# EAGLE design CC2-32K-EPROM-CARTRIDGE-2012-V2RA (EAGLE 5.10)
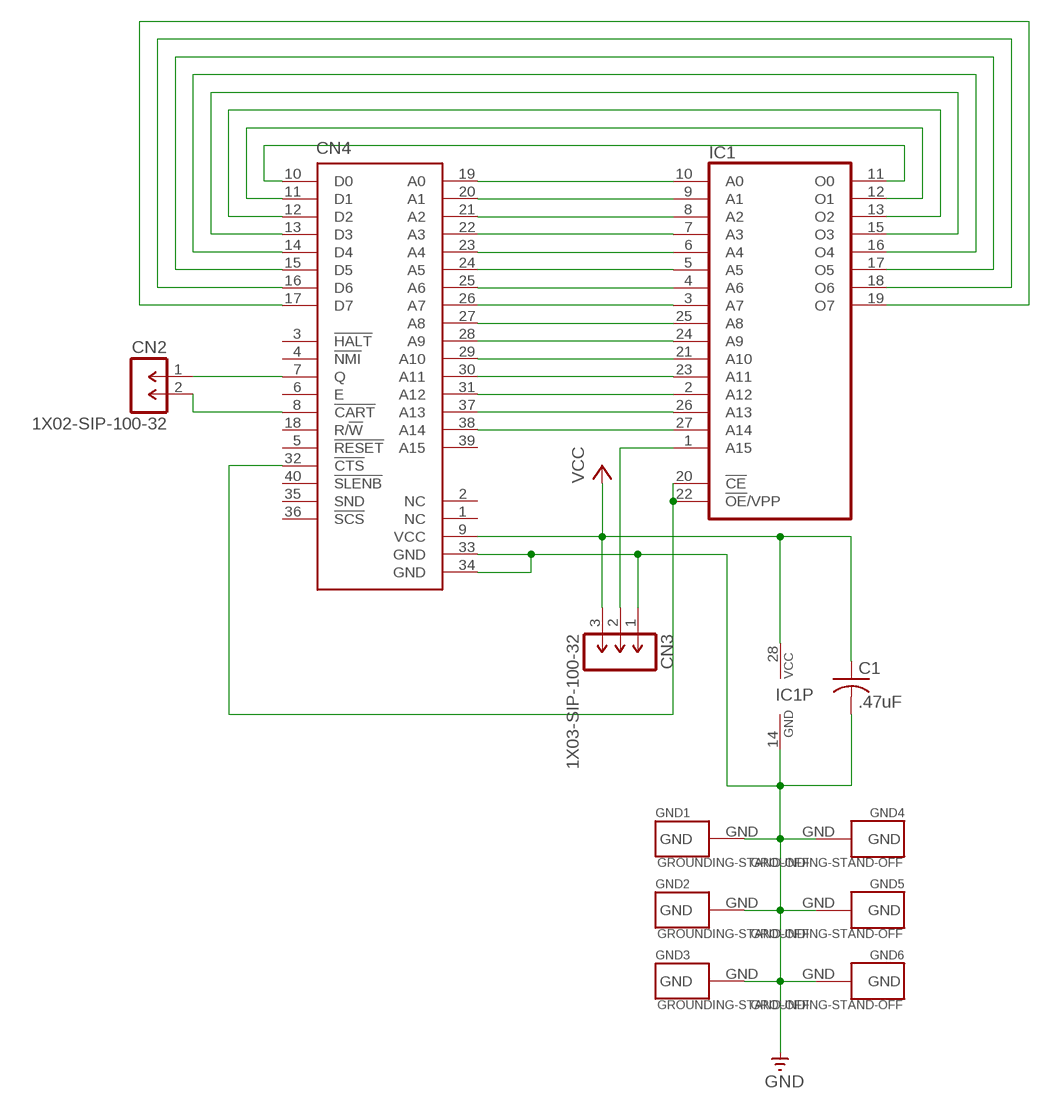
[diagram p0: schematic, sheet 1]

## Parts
C1  .47uF  NP-CAPACITOR-C050-025X075  [C050-025X075]
CN2  1X02-SIP-100-32  [SIL1X02-100]
CN3  1X03-SIP-100-32  [SIL1X03-100]
CN4  COCO3-CARTRIDGE-PLUG-SHORT  [EDGE-CARD-PLUG-2X20-100-SHORT]
GND1  GROUNDING-STAND-OFF  [STAND-OFF]
GND2  GROUNDING-STAND-OFF  [STAND-OFF]
GND3  GROUNDING-STAND-OFF  [STAND-OFF]
GND4  GROUNDING-STAND-OFF  [STAND-OFF]
GND5  GROUNDING-STAND-OFF  [STAND-OFF]
GND6  GROUNDING-STAND-OFF  [STAND-OFF]
IC1  27C512D-MINIMAL-OUTLINE  [DIL28-6-MINIMAL-OUTLINE]

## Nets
GND [power]: C1.2(-) CN3.1 CN4.33(GND) CN4.34(GND) GND1.GND GND2.GND GND3.GND GND4.GND GND5.GND GND6.GND IC1.14(GND)
N$2: CN2.1 CN4.7(Q)
N$3: CN2.2 CN4.8(!CART)
N$4: CN4.19(A0) IC1.10(A0)
N$5: CN4.20(A1) IC1.9(A1)
N$6: CN4.21(A2) IC1.8(A2)
N$7: CN4.22(A3) IC1.7(A3)
N$8: CN4.23(A4) IC1.6(A4)
N$9: CN4.24(A5) IC1.5(A5)
N$10: CN4.25(A6) IC1.4(A6)
N$11: CN4.26(A7) IC1.3(A7)
N$12: CN4.27(A8) IC1.25(A8)
N$13: CN4.28(A9) IC1.24(A9)
N$14: CN4.29(A10) IC1.21(A10)
N$15: CN4.30(A11) IC1.23(A11)
N$16: CN4.31(A12) IC1.2(A12)
N$17: CN4.37(A13) IC1.26(A13)
N$18: CN4.38(A14) IC1.27(A14)
N$19: CN3.2 IC1.1(A15)
N$21: CN4.10(D0) IC1.11(O0)
N$22: CN4.11(D1) IC1.12(O1)
N$23: CN4.12(D2) IC1.13(O2)
N$24: CN4.13(D3) IC1.15(O3)
N$25: CN4.14(D4) IC1.16(O4)
N$26: CN4.15(D5) IC1.17(O5)
N$27: CN4.16(D6) IC1.18(O6)
N$28: CN4.17(D7) IC1.19(O7)
N$29: CN4.32(!CTS) IC1.20(!CE) IC1.22(!OE!/VPP)
VCC [power]: C1.1(+) CN3.3 CN4.9(VCC) IC1.28(VCC)
Unconnected: CN4.1(NC) CN4.2(NC) CN4.3(!HALT) CN4.4(!NMI) CN4.5(!RESET) CN4.6(E) CN4.18(R/!W) CN4.35(SND) CN4.36(!SCS) CN4.39(A15) CN4.40(!SLENB)

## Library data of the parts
C1 = GIMEchip-Capacitor:NP-CAPACITOR: NON-POLARIZED CAPACITOR
CN2 = GIMEchip-Header-Generic:1X02: MALE HEADER
CN3 = GIMEchip-Header-Generic:1X03: MALE HEADER
CN4 = GIMEchip-TRS-80-CoCo-3-Program-Pak-Cartridge:COCO3-CARTRIDGE-PLUG: CoCo 3 Program Pak Cartridge Plug - http://www.GIMEchip.com/ Tandy Radio Shack TRS-80 Color Computer 3 Program Pak Cartridge Plug (Edge-Card) E.A.G.L.E. Library Part created by John Eric Turner & His Father - sales@gimechip.com 40-Pin Edge-Card sharing the same pinout as the Program Pak Cartridge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
GND1-GND6 = GIMEchip-Grounding:GROUNDING
IC1 = GIMEchip-EPROM:27C512D: MEMORY

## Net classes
0 default: width 0.203 mm, clearance 0.203 mm
1 power: width 0.762 mm, clearance 0.203 mm

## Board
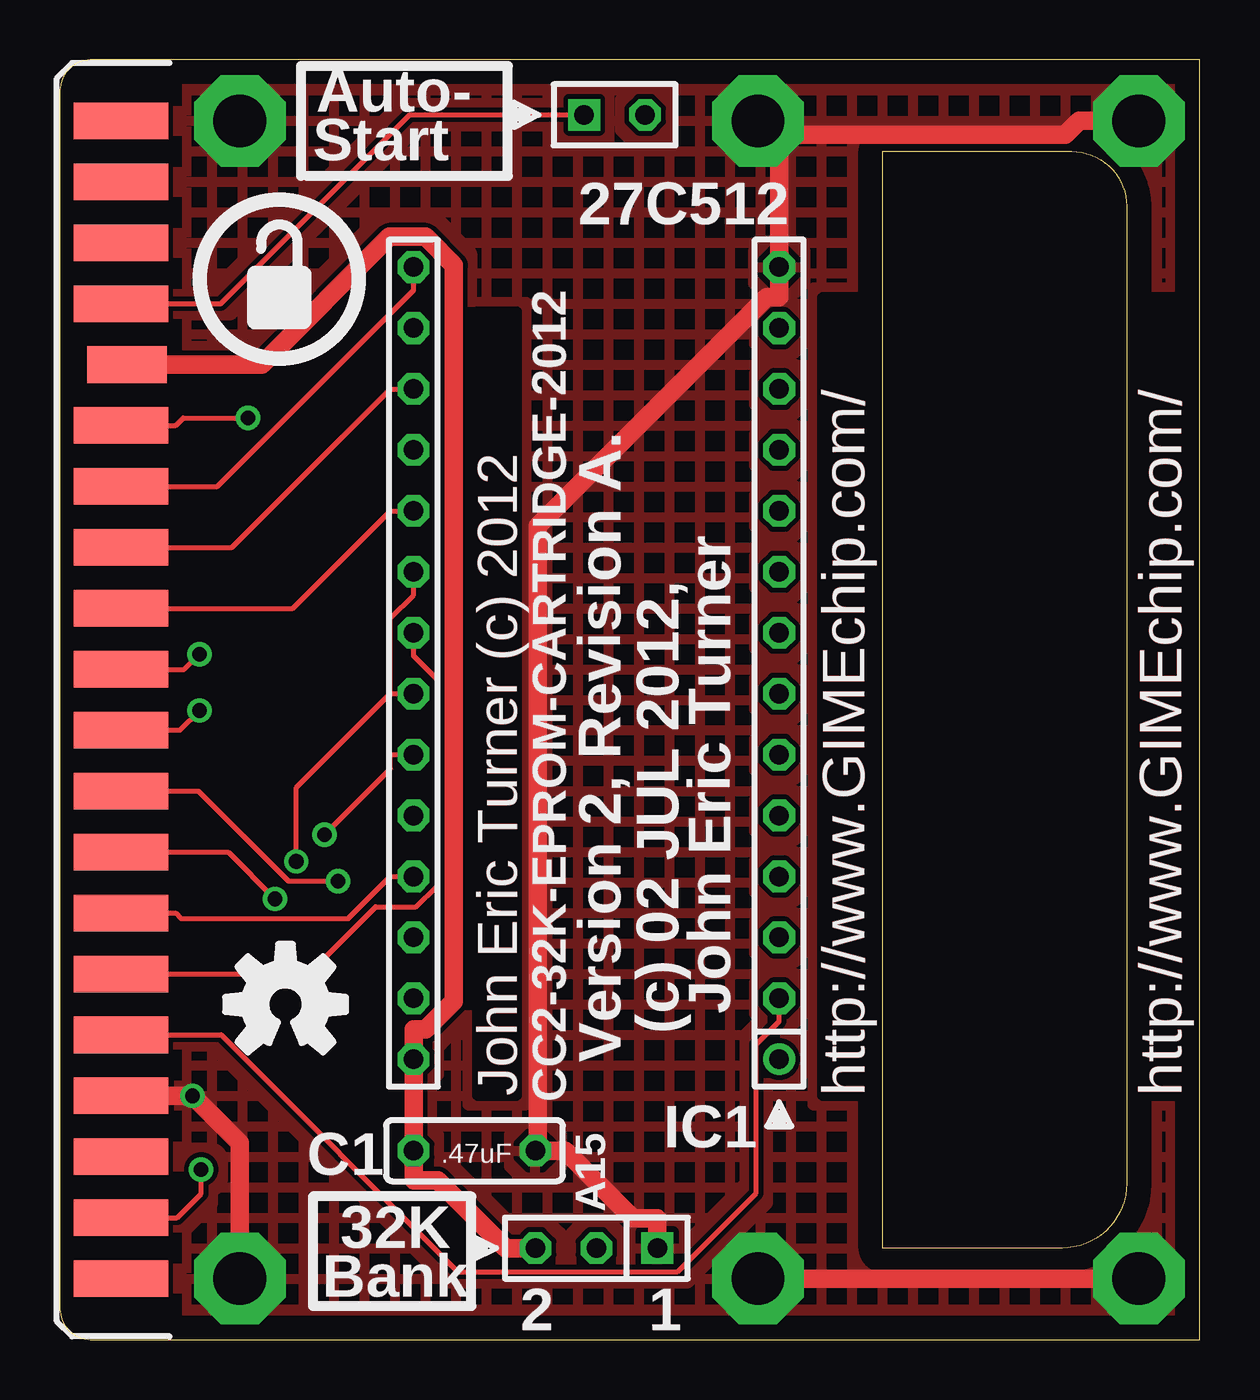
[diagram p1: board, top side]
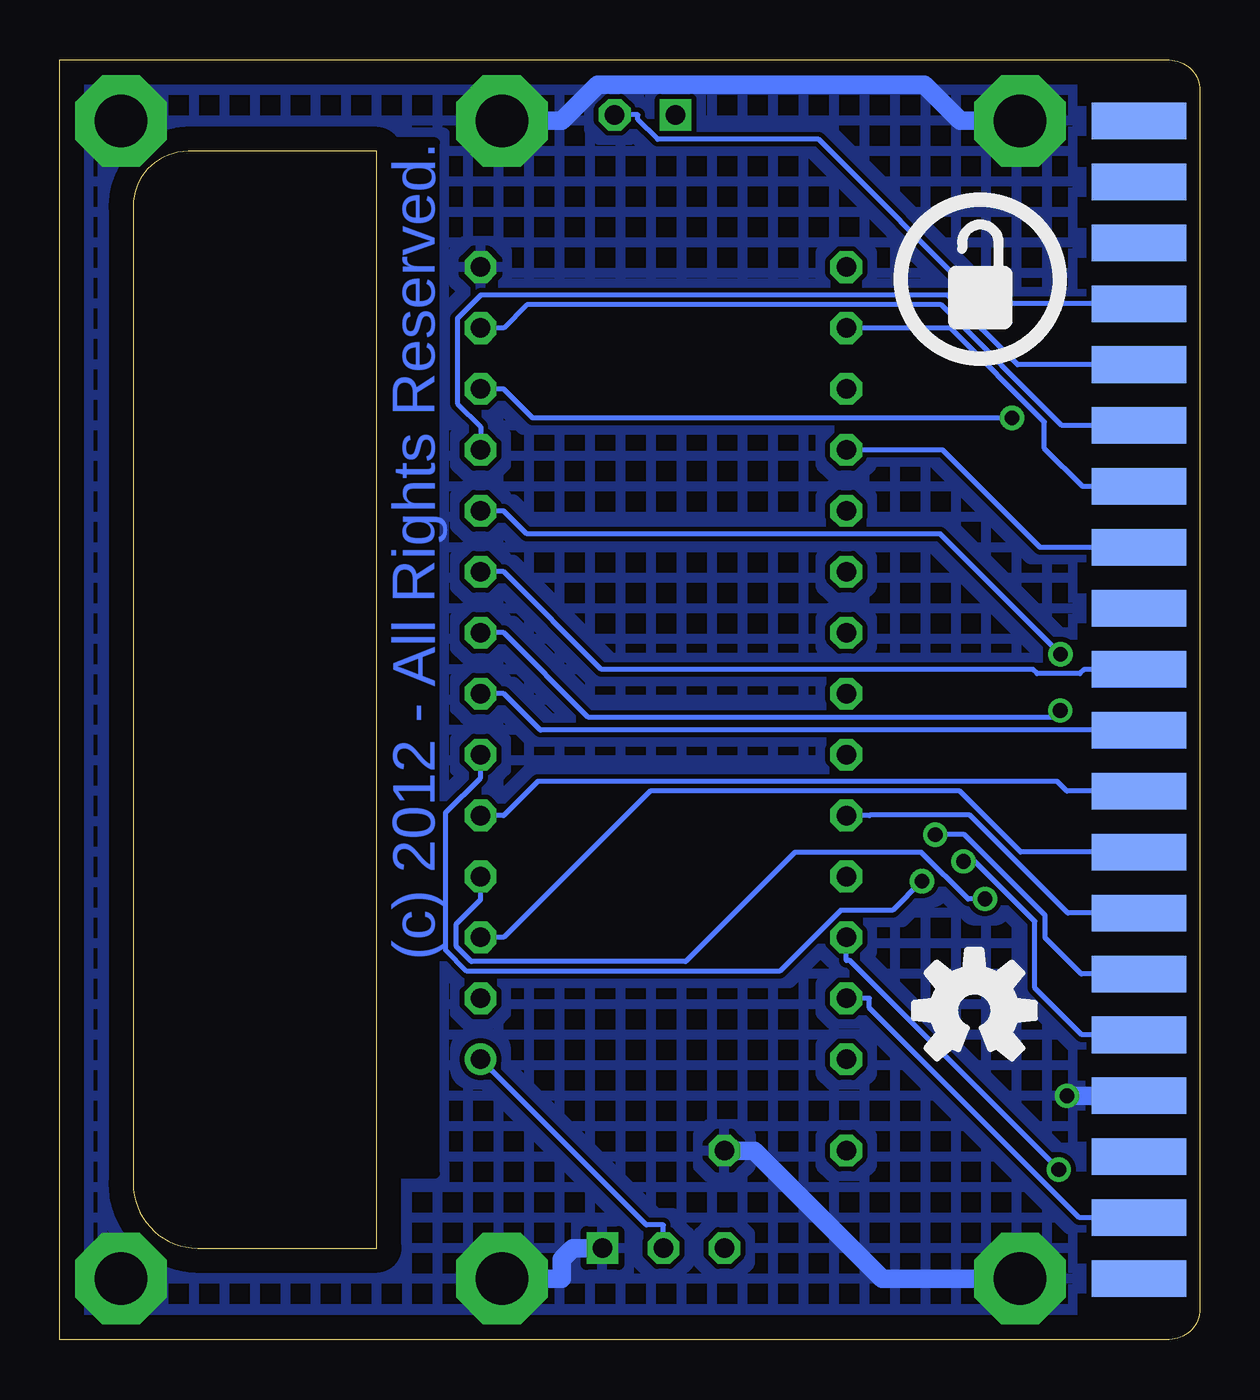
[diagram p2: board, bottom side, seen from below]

Size 47.5 x 53.34 mm. Coordinates in mm from the lower left corner, seen from the top.
Outline: 47.5,0 47.5,53.34 1.27,53.34 arc90 0,52.07 0,1.27 arc90 1.27,0 47.5,0
Outline: 34.29,49.53 42.16,49.53 arc-90 44.45,47.24 44.45,6.5 arc-90 41.76,3.81 34.29,3.81 34.29,49.53
Copper layers (1*16): Top 0.035mm / dielectric 1.5mm / Bottom 0.035mm
Design rules "default": minimum track width 10mil, minimum drill 24mil, track to track 8mil, track to pad 8mil, pad to pad 8mil, via to via 8mil, smd to smd 8mil, copper to edge 40mil, drill to drill 8mil, minimum pad ring 10mil, minimum via ring 8mil, stop-mask expansion 4mil, vias tented up to drill 0mil, thermal gap 10mil
vRestrict: area 15.2,8.9 to 29.2,49.5

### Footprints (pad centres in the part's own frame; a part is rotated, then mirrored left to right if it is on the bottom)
C050-025X075 = drill 0.813 octagon: 1 -2.54,0; 2 2.54,0
SIL1X02-100 = drill 0.813 square: 1 -1.27,0 | drill 0.813 octagon: 2 1.27,0
SIL1X03-100 = drill 0.813 square: 1 -2.54,0 | drill 0.813 octagon: 2 0,0; 3 2.54,0
EDGE-CARD-PLUG-2X20-100-SHORT = smd 3.937 x 1.524: 1 3.81,24.13; 3 3.81,21.59; 5 3.81,19.05; 7 3.81,16.51; 11 3.81,11.43; 13 3.81,8.89; 15 3.81,6.35; 17 3.81,3.81; 19 3.81,1.27; 21 3.81,-1.27; 23 3.81,-3.81; 25 3.81,-6.35; 27 3.81,-8.89; 29 3.81,-11.43; 31 3.81,-13.97; 33 3.81,-16.51; 35 3.81,-19.05; 37 3.81,-21.59; 39 3.81,-24.13 | smd 3.937 x 1.524 bottom: 2 3.81,24.13; 4 3.81,21.59; 6 3.81,19.05; 8 3.81,16.51; 10 3.81,13.97; 12 3.81,11.43; 14 3.81,8.89; 16 3.81,6.35; 18 3.81,3.81; 20 3.81,1.27; 22 3.81,-1.27; 24 3.81,-3.81; 26 3.81,-6.35; 28 3.81,-8.89; 30 3.81,-11.43; 32 3.81,-13.97; 34 3.81,-16.51; 36 3.81,-19.05; 38 3.81,-21.59; 40 3.81,-24.13 | smd 3.302 x 1.524: 9 4.064,13.97
STAND-OFF = drill 2.2 pad 3.81 octagon: GND 0,0
DIL28-6-MINIMAL-OUTLINE = drill 0.813 round: 1 -16.51,-7.62 | drill 0.813 octagon: 2 -13.97,-7.62; 3 -11.43,-7.62; 4 -8.89,-7.62; 5 -6.35,-7.62; 6 -3.81,-7.62; 7 -1.27,-7.62; 8 1.27,-7.62; 9 3.81,-7.62; 10 6.35,-7.62; 11 8.89,-7.62; 12 11.43,-7.62; 13 13.97,-7.62; 14 16.51,-7.62; 15 16.51,7.62; 16 13.97,7.62; 17 11.43,7.62; 18 8.89,7.62; 19 6.35,7.62; 20 3.81,7.62; 21 1.27,7.62; 22 -1.27,7.62; 23 -3.81,7.62; 24 -6.35,7.62; 25 -8.89,7.62; 26 -11.43,7.62; 27 -13.97,7.62; 28 -16.51,7.62

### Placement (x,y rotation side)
C1  17.27,7.87 0 top
CN2  23.11,51.05 0 top
CN3  22.35,3.81 180 top
CN4  -1.27,26.67 0 top
GND1  44.96,50.8 0 top
GND2  44.96,2.54 0 top
GND3  29.08,50.8 0 top
GND4  7.49,50.8 0 top
GND5  29.08,2.54 0 top
GND6  7.49,2.54 0 top
IC1  22.35,28.19 90 top
U$1  [OSHWLOGO_0.3]  9.14,44.2 0 top
U$2  [OSHWLOGO_0.3]  9.14,44.2 0 bottom
U$3  [OSHWLOGO_TOL_0.2]  9.4,13.72 0 bottom
U$4  [OSHWLOGO_TOP_0.2]  9.4,13.97 0 top

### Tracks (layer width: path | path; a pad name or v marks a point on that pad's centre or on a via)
GND  (via drill 0.61 pad 1.02)
  Top 0.762: GND5.GND GND2.GND | 19.91,7.87 19.91,33.91 29.46,43.46 29.97,43.46 IC1.14 29.97,45.95 29.97,50.22 | 19.91,7.87 21.06,7.87 23.88,5.05 24.89,5.05 CN3.1 | C1.2 19.91,7.87 | 29.97,50.22 41.89,50.22 42.47,50.8 GND1.GND | GND3.GND 29.66,50.22 29.97,50.22 | CN4.34 5.09,10.16 v5.53,10.16 7.49,8.19 GND6.GND
  Bottom 0.762: GND3.GND 26.59,50.8 25.09,52.3 11.48,52.3 9.98,50.8 GND4.GND | v5.53,10.16 CN4.34 | GND5.GND 26.59,2.54 26.59,3.35 26.14,3.81 CN3.1 | C1.2 18.57,7.87 13.23,2.54 GND6.GND
  pour Top (hatched): -0.51,53.34 47.5,53.34 47.5,0 -0.51,0
  pour Bottom (hatched): -0.51,53.34 47.5,53.34 47.5,0 -0.51,0
N$2
  Top 0.203: CN4.7 6.69,43.18 14.56,51.05 CN2.1
N$3
  Bottom 0.203: CN4.8 9.04,43.18 15.89,50.03 22.59,50.03 23.42,50.85 23.42,51.05 CN2.2
N$4  (via drill 0.61 pad 1.02)
  Top 0.203: CN4.19 5.17,27.94 v5.81,28.57
  Bottom 0.203: v5.81,28.57 10.81,33.58 28.04,33.58 29.01,34.54 IC1.10
N$5
  Bottom 0.203: CN4.20 4.81,27.94 4.99,27.76 6.78,27.76 6.96,27.94 24.94,27.94 29.01,32 IC1.9
N$6  (via drill 0.61 pad 1.02)
  Top 0.203: CN4.21 4.99,25.4 v5.81,26.22
  Bottom 0.203: IC1.8 29.01,29.46 25.48,25.94 6.1,25.94 v5.81,26.22
N$7
  Bottom 0.203: IC1.7 29.01,26.92 27.48,25.4 CN4.22
N$8  (via drill 0.61 pad 1.02)
  Top 0.203: v11.58,19.11 9.52,19.11 5.77,22.86 CN4.23
  Bottom 0.203: IC1.6 29.97,23.42 31.43,21.96 31.43,16.23 30.55,15.35 17.51,15.35 14.97,17.89 12.8,17.89 v11.58,19.11
N$9
  Bottom 0.203: IC1.5 29.01,21.84 27.58,23.27 5.95,23.27 5.54,22.86 CN4.24
N$10  (via drill 0.61 pad 1.02)
  Top 0.203: CN4.25 7,20.32 v8.96,18.36
  Bottom 0.203: IC1.4 29.97,18.34 30.98,17.33 30.98,16.38 30.36,15.76 21.42,15.76 16.87,20.31 11.6,20.31 9.66,18.36 v8.96,18.36
N$11
  Bottom 0.203: CN4.26 7.46,20.32 10,22.86 22.91,22.86 29.01,16.76 IC1.3
N$12
  Top 0.203: IC1.25 13.77,19.3 12.01,17.55 5.04,17.55 4.81,17.78 CN4.27
N$13
  Bottom 0.203: CN4.28 5.5,17.78 9.58,21.86 13.75,21.86 13.77,21.84 IC1.24
N$14
  Top 0.203: CN4.29 10.36,15.24 13.15,18.03 14.83,18.03 15.71,18.92 15.71,27.52 14.73,28.5 IC1.21
N$15  (via drill 0.61 pad 1.02)
  Top 0.203: IC1.23 13.77,24.38 13.77,23.79 v11.03,21.05
  Bottom 0.203: v11.03,21.05 9.82,21.05 6.45,17.68 6.45,16.75 4.93,15.24 CN4.30
N$16
  Top 0.203: IC1.2 29.97,13.26 29.01,12.29 29.01,6.1 25.74,2.83 16.59,2.83 6.72,12.7 CN4.31
N$17  (via drill 0.61 pad 1.02)
  Top 0.203: v5.88,7.09 5.88,6.08 4.88,5.08 CN4.37
  Bottom 0.203: IC1.26 14.73,15.8 14.59,15.8 v5.88,7.09
N$18
  Bottom 0.203: CN4.38 5.02,5.08 13.77,13.83 13.77,14.22 IC1.27
N$19
  Bottom 0.203: CN3.2 22.35,4.77 23.06,4.77 IC1.1
N$21
  Bottom 0.203: IC1.11 29.97,38.05 30.94,39.02 30.94,42.56 29.96,43.54 10.49,43.54 7.6,40.64 CN4.10
N$22  (via drill 0.61 pad 1.02)
  Top 0.203: v7.83,38.42 5.13,38.42 4.81,38.1 CN4.11
  Bottom 0.203: IC1.12 29.01,39.62 27.8,38.42 v7.83,38.42
N$23
  Bottom 0.203: CN4.12 5.75,38.1 10.78,43.13 28.04,43.13 29.01,42.16 IC1.13
N$24
  Top 0.203: IC1.15 14.73,43.74 6.55,35.56 CN4.13
N$25
  Bottom 0.203: 13.77,42.16 IC1.16 | CN4.14 4.89,35.56 6.47,37.14 6.47,38.25 10.39,42.16 13.77,42.16 | 13.77,42.16
N$26
  Top 0.203: IC1.17 13.77,39.62 7.16,33.02 CN4.15
N$27
  Bottom 0.203: IC1.18 10.72,37.08 6.65,33.02 CN4.16
N$28
  Top 0.203: IC1.19 13.77,34.54 9.7,30.48 CN4.17
N$29  (via drill 0.61 pad 1.02)
  Top 0.203: 13.77,26.92 13.77,30.07 14.73,31.04 IC1.20 | v9.85,19.93 9.85,23 13.77,26.92 | 13.77,26.92 IC1.22
  Bottom 0.203: v9.85,19.93 9.37,19.93 6.88,17.43 6.88,14.66 4.92,12.7 CN4.32
VCC
  Top 0.762: CN4.9 8.4,40.64 13.72,45.97 15.23,45.97 16.41,44.78 16.41,14.1 15.25,12.93 14.73,12.93 IC1.28 C1.1 14.73,6.63 15.75,6.63 18.57,3.81 CN3.3

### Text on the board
Top: John Eric Turner (c) 2012 | http://www.GIMEchip.com/ | http://www.GIMEchip.com/
Bottom: (c) 2012 - All Rights Reserved.
tNames: Auto- | Start | 27C512 | GND3 | C1 | CN2 | CN3 | GND1 | GND2 | IC1 | CN4 | GND4 | GND6 | GND5 | John Eric Turner | (c) 02 JUL 2012, | Version 2, Revision A. | John Eric Turner (c) 2012 | http://www.GIMEchip.com/ | http://www.GIMEchip.com/ | CC2-32K-EPROM-CARTRIDGE-2012 | IC1 | C1 | A15 | 32K | Bank | 2 | 1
